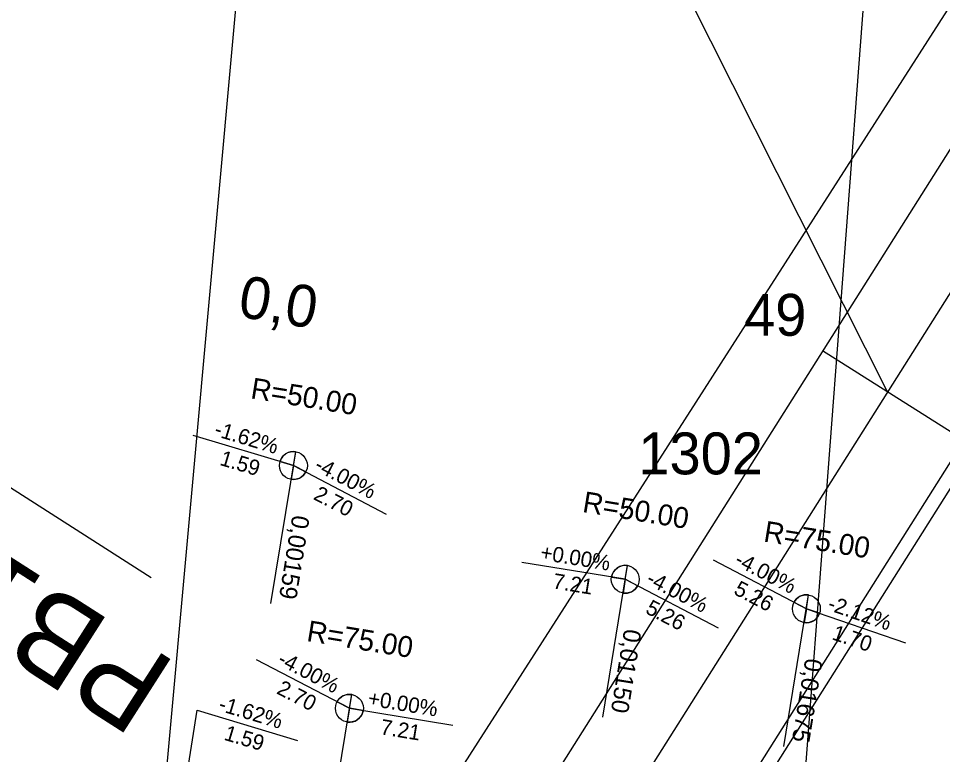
# Model space of a CAD drawing. Extents: x -743546 to -74, y -1128126 to -103.
# Drawn here: x -743185.96 to -743159.49, y -1127087.52 to -1127066.44 of the extents above; entities that cross this region are included whole.
import ezdxf

# ---------------------------------------------------------------- set-up
doc = ezdxf.new("R2010")
doc.units = 0
for name, color, linetype in [('_Zabezpečovací zařízení_trasa', 7, 'Continuous'), ('bublina_fialová_čára_tenká', 7, 'Continuous'), ('křížky', 7, 'Continuous'), ('Nový stav', 7, 'Continuous'), ('OSA_POP', 7, 'Continuous'), ('SKLONOVNIKY', 7, 'Continuous'), ('SMER_VYS_VYROVNANI', 7, 'Continuous'), ('TRATIVOD', 7, 'Continuous'), ('Vrstva 53', 7, 'Continuous'), ('Vrstva 60', 7, 'Continuous')]:
    doc.layers.add(name, color=color, linetype=linetype)

# ---------------------------------------------------------------- blocks, each defined once
blk = doc.blocks.new('POINT_DISPLAY')
blk.add_line((0, 0), (0, 0))
blk = doc.blocks.new('AeccTickCircle')
blk.add_circle((0, 0), 0.5)

msp = doc.modelspace()

# ---------------------------------------------------------------- linework, layer by layer
at = {"layer": '_Zabezpečovací zařízení_trasa'}
msp.add_line((-743155.94, -1127080.38), (-743162.932, -1127075.966), dxfattribs=at)
for points in [[(-743049.28, -1126895.951), (-743072.487, -1126932.751), (-743098.647, -1126974.146), (-743125.94, -1127017.384), (-743152.604, -1127059.608), (-743175.023, -1127095.116), (-743199.163, -1127133.346), (-743215.971, -1127159.941), (-743232.818, -1127186.515), (-743247.456, -1127209.811), (-743254.52, -1127221.639), (-743261.299, -1127233.691), (-743264.155, -1127239.195), (-743264.862, -1127241.108), (-743267.337, -1127245.816)], [(-743164.036, -1127096.193), (-743163.862, -1127095.231), (-743167.492, -1127092.937), (-743158.53, -1127078.745)]]:
    msp.add_lwpolyline(points, dxfattribs=at)
at = {"layer": 'bublina_fialová_čára_tenká'}
for p, q in [((-743158.823, -1127027.044), (-743164.286, -1127099.423)), ((-743177.808, -1127044.792), (-743182.5, -1127096.45))]:
    msp.add_line(p, q, dxfattribs=at)
at = {"layer": 'Nový stav'}
for p, q in [((-743161.072, -1127077.14), (-743168.127, -1127063.114)), ((-743161.072, -1127077.14), (-743168.127, -1127063.114)), ((-743182.166, -1127082.459), (-743203.226, -1127068.988)), ((-743182.166, -1127082.459), (-743203.226, -1127068.988))]:
    msp.add_line(p, q, dxfattribs=at)
at = {"layer": 'SKLONOVNIKY'}
for p, q in [((-743178.088, -1127079.247), (-743180.961, -1127078.386)), ((-743178.731, -1127083.195), (-743178.023, -1127078.853)), ((-743178.088, -1127079.247), (-743175.428, -1127080.636)), ((-743168.582, -1127082.505), (-743171.543, -1127082.023)), ((-743169.225, -1127086.453), (-743168.517, -1127082.11)), ((-743163.394, -1127083.35), (-743166.053, -1127081.961)), ((-743168.582, -1127082.505), (-743165.922, -1127083.894)), ((-743164.037, -1127087.298), (-743163.33, -1127082.955)), ((-743163.394, -1127083.35), (-743160.557, -1127084.326)), ((-743176.483, -1127086.201), (-743179.142, -1127084.812)), ((-743177.126, -1127090.149), (-743176.418, -1127085.806)), ((-743181.483, -1127090.206), (-743180.84, -1127086.258)), ((-743180.84, -1127086.258), (-743177.967, -1127087.12)), ((-743176.483, -1127086.201), (-743173.522, -1127086.683))]:
    msp.add_line(p, q, dxfattribs=at)
for points in [[(-743178.471, -1127079.132), (-743178.088, -1127079.247), (-743178.023, -1127078.853)], [(-743177.733, -1127079.432), (-743178.088, -1127079.247), (-743178.152, -1127079.642)], [(-743168.977, -1127082.441), (-743168.582, -1127082.505), (-743168.517, -1127082.11)], [(-743168.227, -1127082.69), (-743168.582, -1127082.505), (-743168.646, -1127082.9)], [(-743163.749, -1127083.164), (-743163.394, -1127083.35), (-743163.33, -1127082.955)], [(-743163.016, -1127083.48), (-743163.394, -1127083.35), (-743163.458, -1127083.744)], [(-743176.837, -1127086.016), (-743176.483, -1127086.201), (-743176.418, -1127085.806)], [(-743176.088, -1127086.265), (-743176.483, -1127086.201), (-743176.547, -1127086.596)]]:
    msp.add_lwpolyline(points, dxfattribs=at)
for centre, start, end in [((-743178.088, -1127079.247), 80.752, 163.3077), ((-743178.088, -1127079.247), 260.752, 332.4271), ((-743168.582, -1127082.505), 80.752, 170.752), ((-743168.582, -1127082.505), 260.752, 332.4271), ((-743163.394, -1127083.35), 80.752, 152.4271), ((-743163.394, -1127083.35), 260.752, 341.0149), ((-743176.483, -1127086.201), 80.752, 152.4271), ((-743176.483, -1127086.201), 260.752, 350.752)]:
    msp.add_arc(centre, 0.4, start, end, dxfattribs=at)
at = {"layer": 'SMER_VYS_VYROVNANI'}
msp.add_lwpolyline([(-743143.427, -1127049.192), (-743169.53, -1127090.542)], dxfattribs=at)
at = {"layer": 'TRATIVOD'}
msp.add_lwpolyline([(-743175.637, -1127105.086), (-743168.399, -1127093.621), (-743157.384, -1127076.172), (-743151.775, -1127072.311)], dxfattribs=at)
at = {"layer": 'Vrstva 53'}
msp.add_lwpolyline([(-743032.8, -1126884.17), (-743063.8, -1126932.98), (-743082.27, -1126962.07), (-743093.1, -1126978.92), (-743136.47, -1127047.12), (-743147.78, -1127068.8), (-743159.64, -1127094.74), (-743160.17, -1127095.91), (-743166.78, -1127095.57), (-743176.42, -1127093.47), (-743180.17, -1127093.19), (-743180.08, -1127092.14), (-743178.51, -1127091.81), (-743175.35, -1127091.16), (-743150.075, -1127051.72), (-743124.8, -1127012.28), (-743108.67, -1126985.4), (-743080.97, -1126930.41), (-743079.79, -1126928.05), (-743048.51, -1126865.51)], dxfattribs=at)
at = {"layer": 'Vrstva 60'}
for p, q in [((-743162.932, -1127075.966), (-743162.932, -1127075.966)), ((-743164.248, -1127082.175), (-743164.248, -1127082.175))]:
    msp.add_line(p, q, dxfattribs=at)

# ---------------------------------------------------------------- block references
at = {"layer": 'křížky', "xscale": 10, "yscale": 10, "rotation": 61.14491455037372}
for p in [(-743162.932, -1127075.966), (-743164.248, -1127082.175)]:
    msp.add_blockref('POINT_DISPLAY', p, dxfattribs=at)
at = {"layer": 'SKLONOVNIKY', "xscale": 0.8, "yscale": 0.7999999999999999, "rotation": 80.75200331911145}
for p in [(-743178.088, -1127079.247), (-743168.582, -1127082.505), (-743163.394, -1127083.35), (-743176.483, -1127086.201)]:
    msp.add_blockref('AeccTickCircle', p, dxfattribs=at)

# ---------------------------------------------------------------- texts
at = {"layer": 'Nový stav'}
msp.add_text('PB17 km 12,985', height=2.5, rotation=147.395, dxfattribs=at).set_placement((-743181.381, -1127084.936))
msp.add_text('PB17 km 12,985', height=2.5, rotation=147.395, dxfattribs=at).set_placement((-743181.381, -1127084.936))
at = {"layer": 'OSA_POP'}
msp.add_text('0,0', height=1.2, rotation=350.752, dxfattribs=at).set_placement((-743179.708, -1127074.975))
at = {"layer": 'SKLONOVNIKY'}
for s, height, rotation, p in [('R=50.00', 0.6, 350.752, (-743179.337, -1127077.318)), ('-1.62%', 0.44, 343.3077, (-743180.382, -1127078.386)), ('1.59', 0.44, 343.3077, (-743180.222, -1127079.225)), ('-4.00%', 0.44, 332.4271, (-743177.519, -1127079.357)), ('2.70', 0.44, 332.4271, (-743177.541, -1127080.2)), ('R=50.00', 0.6, 350.752, (-743169.831, -1127080.575)), ('0,00159', 0.5, 260.752, (-743178.114, -1127080.647)), ('R=75.00', 0.6, 350.752, (-743164.643, -1127081.42)), ('+0.00%', 0.44, 350.752, (-743171.037, -1127081.937)), ('-4.00%', 0.44, 332.4271, (-743165.484, -1127082.071)), ('7.21', 0.44, 350.752, (-743170.677, -1127082.763)), ('-4.00%', 0.44, 332.4271, (-743168.013, -1127082.615)), ('5.26', 0.44, 332.4271, (-743165.504, -1127082.915)), ('5.26', 0.44, 332.4271, (-743168.032, -1127083.459)), ('-2.12%', 0.44, 341.0149, (-743162.815, -1127083.373)), ('R=75.00', 0.6, 350.752, (-743177.732, -1127084.271)), ('0,01150', 0.5, 260.752, (-743168.609, -1127083.907)), ('1.70', 0.44, 341.0149, (-743162.688, -1127084.218)), ('-4.00%', 0.44, 332.4271, (-743178.573, -1127084.922)), ('0,01675', 0.5, 260.752, (-743163.42, -1127084.746)), ('2.70', 0.44, 332.4271, (-743178.595, -1127085.765)), ('+0.00%', 0.44, 350.752, (-743175.977, -1127086.115)), ('-1.62%', 0.44, 343.3077, (-743180.261, -1127086.258)), ('7.21', 0.44, 350.752, (-743175.617, -1127086.941)), ('1.59', 0.44, 343.3077, (-743180.101, -1127087.097))]:
    msp.add_text(s, height=height, rotation=rotation, dxfattribs=at).set_placement(p)
at = {"layer": 'Vrstva 60'}
for s, p in [('49', (-743165.179, -1127075.531)), ('1302', (-743168.207, -1127079.5))]:
    msp.add_text(s, height=1.2, dxfattribs=at).set_placement(p)

doc.saveas('drawing.dxf')
